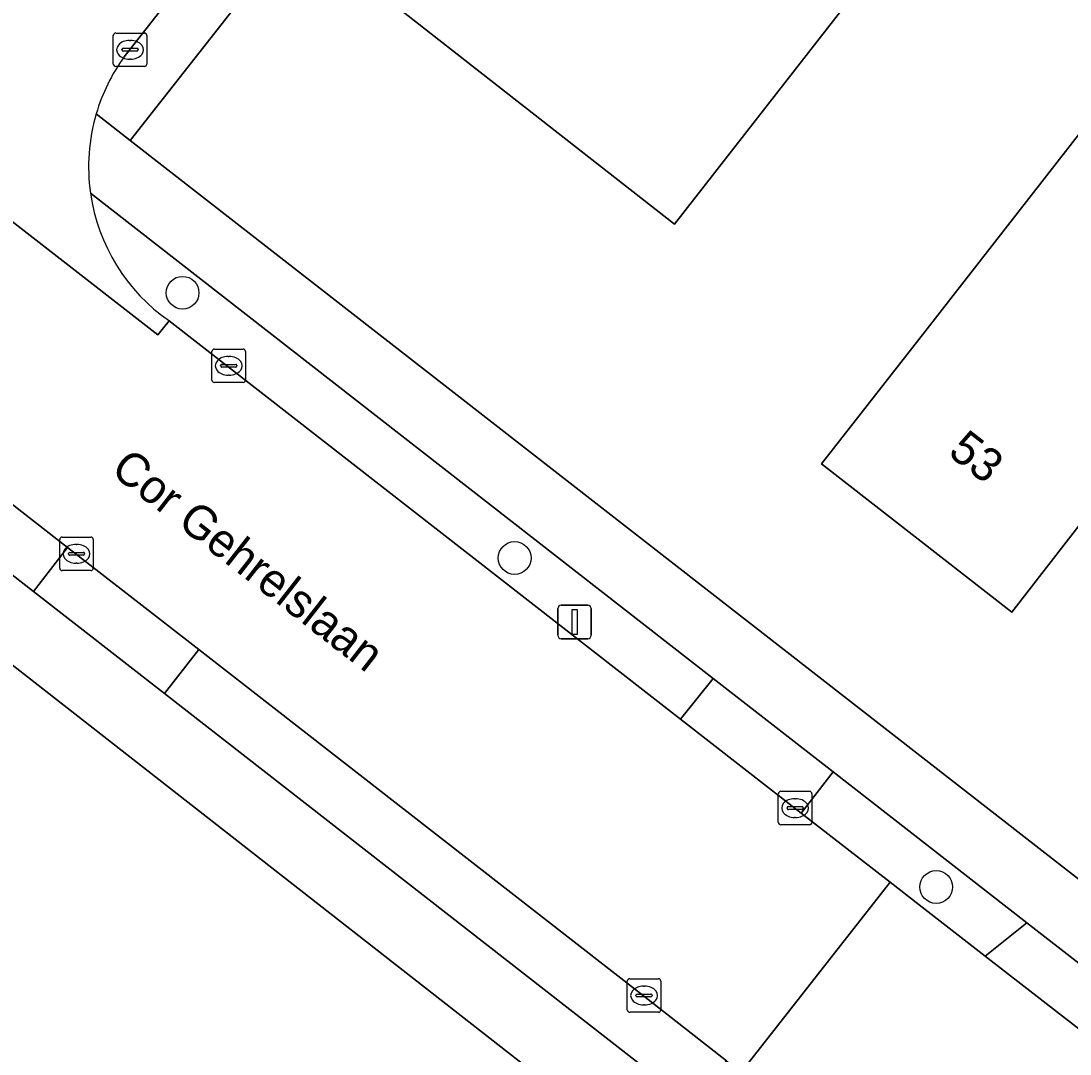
# Model space of a CAD drawing. Extents: x 157320 to 158835, y 386650 to 388491.
# Drawn here: x 158075.99 to 158107.28, y 387187.07 to 387217.9 of the extents above; entities that cross this region are included whole.
import ezdxf

# ---------------------------------------------------------------- set-up
doc = ezdxf.new("R2010")
doc.units = 0
for name, color, linetype in [('IMGEO_Boom', 7, 'Continuous'), ('IMGEO_Erf', 7, 'Continuous'), ('IMGEO_Groenvoorziening', 7, 'Continuous'), ('IMGEO_Kolk', 7, 'Continuous'), ('IMGEO_Lichtmast', 7, 'Continuous'), ('IMGEO_Openbare_ruimte_label', 7, 'Continuous'), ('IMGEO_Pand', 7, 'Continuous'), ('IMGEO_Pand_nummerreeks', 7, 'Continuous'), ('IMGEO_Rijbaan_lokaal_gesloten', 7, 'Continuous'), ('IMGEO_Voetpad_open', 7, 'Continuous')]:
    doc.layers.add(name, color=color, linetype=linetype)

msp = doc.modelspace()

# ---------------------------------------------------------------- linework, layer by layer
at = {"layer": 'IMGEO_Boom'}
for centre in [(158080.808, 387209.792), (158090.712, 387201.874), (158103.289, 387192.056)]:
    msp.add_circle(centre, 0.489, dxfattribs=at)
at = {"layer": 'IMGEO_Erf'}
for points in [[(158090.73, 387228.956), (158079.248, 387214.335), (158109.367, 387190.866), (158137.628, 387206.813)], [(158017.427, 387142.155), (158094.77, 387183.795), (158072.482, 387201.21), (158048.683, 387219.809)]]:
    msp.add_lwpolyline(points, dxfattribs=at)
for points in [[(158103.393, 387218.736), (158101.816, 387219.965), (158095.482, 387211.842), (158086.534, 387218.851), (158093.075, 387227.199), (158096.908, 387224.21), (158099.042, 387226.947), (158105.73, 387221.733)], [(158123.343, 387208.428), (158120.263, 387204.488), (158117.317, 387206.788), (158111.629, 387199.508), (158108.879, 387201.613), (158109.61, 387202.545), (158108.198, 387203.684), (158105.549, 387200.261), (158099.868, 387204.686), (158102.945, 387208.628), (158107.675, 387214.687), (158113.108, 387210.445), (158116.944, 387215.359), (158124.283, 387209.63)]]:
    msp.add_lwpolyline(points, close=True, dxfattribs=at)
at = {"layer": 'IMGEO_Groenvoorziening'}
for points in [[(158078.231, 387215.128), (158079.248, 387214.335), (158090.73, 387228.956), (158089.404, 387230.023), (158079.065, 387216.835)], [(158080.412, 387208.951), (158095.66, 387197.062), (158096.631, 387198.279), (158093.932, 387200.386), (158078.059, 387212.761)], [(158110.765, 387187.271), (158105.993, 387190.987), (158104.752, 387189.993), (158108.123, 387187.373)]]:
    msp.add_lwpolyline(points, dxfattribs=at)
for points in [[(158072.002, 387206.373), (158070.97, 387205.047), (158073.757, 387202.905), (158076.355, 387200.879), (158077.374, 387202.189)], [(158081.29, 387199.14), (158080.268, 387197.827), (158095.882, 387185.65), (158097.032, 387186.869), (158094.555, 387188.809)], [(158100.214, 387195.488), (158099.264, 387194.259), (158101.914, 387192.199), (158102.78, 387191.526), (158104.752, 387189.993), (158105.993, 387190.987)]]:
    msp.add_lwpolyline(points, close=True, dxfattribs=at)
for centre, radius, start, end in [((158083.605, 387213.559), 5.599, 144.1924, 163.7295), ((158083.599, 387213.551), 5.596, 188.1131, 235.2846)]:
    msp.add_arc(centre, radius, start, end, dxfattribs=at)
at = {"layer": 'IMGEO_Kolk'}
for p, q in [((158078.815, 387217.544), (158079.667, 387217.544)), ((158078.74, 387216.618), (158078.74, 387217.47)), ((158079.228, 387217.324), (158079.253, 387217.324)), ((158079.741, 387217.47), (158079.741, 387216.618)), ((158078.999, 387217.038), (158078.999, 387217.05)), ((158079.437, 387217.001), (158079.039, 387217.001)), ((158079.042, 387217.087), (158079.44, 387217.087)), ((158079.483, 387217.05), (158079.483, 387217.038)), ((158079.251, 387216.764), (158079.226, 387216.764)), ((158079.667, 387216.544), (158078.815, 387216.544)), ((158081.759, 387208.112), (158082.611, 387208.112)), ((158081.684, 387207.186), (158081.684, 387208.038)), ((158082.172, 387207.892), (158082.197, 387207.892)), ((158082.685, 387208.038), (158082.685, 387207.186)), ((158081.943, 387207.606), (158081.943, 387207.618)), ((158082.381, 387207.569), (158081.983, 387207.569)), ((158081.986, 387207.655), (158082.384, 387207.655)), ((158082.427, 387207.618), (158082.427, 387207.606)), ((158082.195, 387207.332), (158082.17, 387207.332)), ((158082.611, 387207.112), (158081.759, 387207.112)), ((158077.216, 387202.5), (158078.068, 387202.5)), ((158077.141, 387201.574), (158077.141, 387202.426)), ((158077.629, 387202.28), (158077.654, 387202.28)), ((158078.142, 387202.426), (158078.142, 387201.574)), ((158077.4, 387201.994), (158077.4, 387202.006)), ((158077.838, 387201.957), (158077.44, 387201.957)), ((158077.443, 387202.043), (158077.841, 387202.043)), ((158077.884, 387202.006), (158077.884, 387201.994)), ((158077.652, 387201.72), (158077.627, 387201.72)), ((158078.068, 387201.5), (158077.216, 387201.5)), ((158098.579, 387193.985), (158098.579, 387194.837)), ((158098.654, 387194.911), (158099.506, 387194.911)), ((158099.067, 387194.691), (158099.092, 387194.691)), ((158099.58, 387194.837), (158099.58, 387193.985)), ((158098.838, 387194.405), (158098.838, 387194.417)), ((158099.276, 387194.368), (158098.878, 387194.368)), ((158098.881, 387194.454), (158099.279, 387194.454)), ((158099.322, 387194.417), (158099.322, 387194.405)), ((158099.09, 387194.131), (158099.065, 387194.131)), ((158099.506, 387193.911), (158098.654, 387193.911)), ((158094.073, 387188.39), (158094.073, 387189.242)), ((158094.148, 387189.316), (158095, 387189.316)), ((158094.561, 387189.096), (158094.586, 387189.096)), ((158095.074, 387189.242), (158095.074, 387188.39)), ((158094.332, 387188.81), (158094.332, 387188.822)), ((158094.77, 387188.773), (158094.372, 387188.773)), ((158094.375, 387188.859), (158094.773, 387188.859)), ((158094.816, 387188.822), (158094.816, 387188.81)), ((158094.584, 387188.536), (158094.559, 387188.536)), ((158095, 387188.316), (158094.148, 387188.316))]:
    msp.add_line(p, q, dxfattribs=at)
for points in [[(158078.815, 387217.544), (158079.667, 387217.544)], [(158078.74, 387216.618), (158078.74, 387217.47)], [(158079.741, 387217.47), (158079.741, 387216.618)], [(158079.667, 387216.544), (158078.815, 387216.544)], [(158081.759, 387208.112), (158082.611, 387208.112)], [(158081.684, 387207.186), (158081.684, 387208.038)], [(158082.685, 387208.038), (158082.685, 387207.186)], [(158082.611, 387207.112), (158081.759, 387207.112)], [(158077.216, 387202.5), (158078.068, 387202.5)], [(158077.141, 387201.574), (158077.141, 387202.426)], [(158078.142, 387202.426), (158078.142, 387201.574)], [(158078.068, 387201.5), (158077.216, 387201.5)], [(158098.579, 387193.985), (158098.579, 387194.837)], [(158098.654, 387194.911), (158099.506, 387194.911)], [(158099.58, 387194.837), (158099.58, 387193.985)], [(158099.506, 387193.911), (158098.654, 387193.911)], [(158094.073, 387188.39), (158094.073, 387189.242)], [(158094.148, 387189.316), (158095, 387189.316)], [(158095.074, 387189.242), (158095.074, 387188.39)], [(158095, 387188.316), (158094.148, 387188.316)]]:
    msp.add_lwpolyline(points, dxfattribs=at)
for centre, radius, start, end in [((158078.817, 387217.468), 0.0765, 91.552, 178.448), ((158078.817, 387217.468), 0.0765, 91.552, 178.448), ((158079.665, 387217.468), 0.0765, 1.552, 88.448), ((158079.665, 387217.468), 0.0765, 1.552, 88.448), ((158079.039, 387217.047), 0.0403, 85.8775, 175.7526), ((158079.036, 387217.037), 0.0366, 178.938, 274.7102), ((158079.44, 387217.044), 0.043, 264.8664, 352.4533), ((158079.444, 387217.049), 0.0386, 1.7309, 96.639), ((158078.817, 387216.62), 0.0765, 181.552, 268.448), ((158078.817, 387216.62), 0.0765, 181.552, 268.448), ((158079.665, 387216.62), 0.0765, 271.552, 358.448), ((158079.665, 387216.62), 0.0765, 271.552, 358.448), ((158081.761, 387208.036), 0.0765, 91.552, 178.448), ((158081.761, 387208.036), 0.0765, 91.552, 178.448), ((158082.609, 387208.036), 0.0765, 1.552, 88.448), ((158082.609, 387208.036), 0.0765, 1.552, 88.448), ((158081.983, 387207.615), 0.0403, 85.8775, 175.7526), ((158081.98, 387207.605), 0.0366, 178.938, 274.7102), ((158082.384, 387207.612), 0.043, 264.8664, 352.4533), ((158082.388, 387207.617), 0.0386, 1.7309, 96.639), ((158081.761, 387207.188), 0.0765, 181.552, 268.448), ((158081.761, 387207.188), 0.0765, 181.552, 268.448), ((158082.609, 387207.188), 0.0765, 271.552, 358.448), ((158082.609, 387207.188), 0.0765, 271.552, 358.448), ((158077.218, 387202.424), 0.0765, 91.552, 178.448), ((158077.218, 387202.424), 0.0765, 91.552, 178.448), ((158078.066, 387202.424), 0.0765, 1.552, 88.448), ((158078.066, 387202.424), 0.0765, 1.552, 88.448), ((158077.44, 387202.003), 0.0403, 85.8775, 175.7526), ((158077.437, 387201.993), 0.0366, 178.938, 274.7102), ((158077.841, 387202), 0.043, 264.8664, 352.4533), ((158077.845, 387202.005), 0.0386, 1.7309, 96.639), ((158077.218, 387201.576), 0.0765, 181.552, 268.448), ((158077.218, 387201.576), 0.0765, 181.552, 268.448), ((158078.066, 387201.576), 0.0765, 271.552, 358.448), ((158078.066, 387201.576), 0.0765, 271.552, 358.448), ((158098.656, 387194.835), 0.0765, 91.552, 178.448), ((158098.656, 387194.835), 0.0765, 91.552, 178.448), ((158099.504, 387194.835), 0.0765, 1.552, 88.448), ((158099.504, 387194.835), 0.0765, 1.552, 88.448), ((158098.878, 387194.414), 0.0403, 85.8775, 175.7526), ((158098.875, 387194.404), 0.0366, 178.938, 274.7102), ((158099.279, 387194.411), 0.043, 264.8664, 352.4533), ((158099.283, 387194.416), 0.0386, 1.7309, 96.639), ((158098.656, 387193.987), 0.0765, 181.552, 268.448), ((158098.656, 387193.987), 0.0765, 181.552, 268.448), ((158099.504, 387193.987), 0.0765, 271.552, 358.448), ((158099.504, 387193.987), 0.0765, 271.552, 358.448), ((158094.15, 387189.24), 0.0765, 91.552, 178.448), ((158094.15, 387189.24), 0.0765, 91.552, 178.448), ((158094.998, 387189.24), 0.0765, 1.552, 88.448), ((158094.998, 387189.24), 0.0765, 1.552, 88.448), ((158094.372, 387188.819), 0.0403, 85.8775, 175.7526), ((158094.369, 387188.809), 0.0366, 178.938, 274.7102), ((158094.773, 387188.816), 0.043, 264.8664, 352.4533), ((158094.777, 387188.821), 0.0386, 1.7309, 96.639), ((158094.15, 387188.392), 0.0765, 181.552, 268.448), ((158094.15, 387188.392), 0.0765, 181.552, 268.448), ((158094.998, 387188.392), 0.0765, 271.552, 358.448), ((158094.998, 387188.392), 0.0765, 271.552, 358.448)]:
    msp.add_arc(centre, radius, start, end, dxfattribs=at)
for centre, major_axis, ratio, start_param, end_param in [((158079.227, 387217.044), (-0.387, 0.002), 0.722429, 4.712389, 7.853982), ((158079.252, 387217.044), (-0.39, 0.002), 0.717154, 1.570796, 4.712389), ((158082.171, 387207.612), (-0.387, 0.002), 0.722429, 4.712389, 7.853982), ((158082.196, 387207.612), (-0.39, 0.002), 0.717154, 1.570796, 4.712389), ((158077.628, 387202), (-0.387, 0.002), 0.722429, 4.712389, 7.853982), ((158077.653, 387202), (-0.39, 0.002), 0.717154, 1.570796, 4.712389), ((158099.066, 387194.411), (-0.387, 0.002), 0.722429, 4.712389, 7.853982), ((158099.091, 387194.411), (-0.39, 0.002), 0.717154, 1.570796, 4.712389), ((158094.56, 387188.816), (-0.387, 0.002), 0.722429, 4.712389, 7.853982), ((158094.585, 387188.816), (-0.39, 0.002), 0.717154, 1.570796, 4.712389)]:
    msp.add_ellipse(centre, major_axis=major_axis, ratio=ratio, start_param=start_param, end_param=end_param, dxfattribs=at)
at = {"layer": 'IMGEO_Lichtmast'}
for p, q in [((158092.005, 387199.567), (158092.005, 387200.367)), ((158092.005, 387200.367), (158092.005, 387199.567)), ((158092.105, 387200.467), (158092.895, 387200.467)), ((158092.895, 387200.467), (158092.105, 387200.467)), ((158092.995, 387200.367), (158092.995, 387199.567)), ((158092.995, 387199.567), (158092.995, 387200.367)), ((158092.895, 387199.467), (158092.105, 387199.467)), ((158092.105, 387199.467), (158092.895, 387199.467))]:
    msp.add_line(p, q, dxfattribs=at)
msp.add_lwpolyline([(158092.425, 387200.342), (158092.575, 387200.342), (158092.575, 387199.592), (158092.425, 387199.592), (158092.425, 387200.342)], dxfattribs=at)
for centre, start, end in [((158092.105, 387200.367), 90, 180), ((158092.105, 387200.367), 90, 180), ((158092.895, 387200.367), 0, 90), ((158092.895, 387200.367), 360, 90), ((158092.105, 387199.567), 180, 270), ((158092.105, 387199.567), 180, 270), ((158092.895, 387199.567), 270, 0), ((158092.895, 387199.567), 270, 0)]:
    msp.add_arc(centre, 0.1, start, end, dxfattribs=at)
at = {"layer": 'IMGEO_Pand'}
for points in [[(158095.482, 387211.842), (158101.816, 387219.965), (158103.393, 387218.736), (158105.73, 387221.733), (158099.042, 387226.947), (158096.908, 387224.21), (158093.075, 387227.199), (158086.534, 387218.851)], [(158102.945, 387208.628), (158099.868, 387204.686), (158105.549, 387200.261), (158108.198, 387203.684), (158109.61, 387202.545), (158108.879, 387201.613), (158111.629, 387199.508), (158117.317, 387206.788), (158120.263, 387204.488), (158123.343, 387208.428), (158124.283, 387209.63), (158116.944, 387215.359), (158113.108, 387210.445), (158107.675, 387214.687)]]:
    msp.add_lwpolyline(points, close=True, dxfattribs=at)
at = {"layer": 'IMGEO_Rijbaan_lokaal_gesloten'}
for points in [[(158079.065, 387216.835), (158089.404, 387230.023), (158091.841, 387233.164), (158105.03, 387250), (158110.984, 387257.602)], [(158051.069, 387222.744), (158066.919, 387210.32), (158072.002, 387206.373), (158077.374, 387202.189), (158081.29, 387199.14), (158094.555, 387188.809), (158097.032, 387186.869), (158097.47, 387186.526), (158101.914, 387192.199), (158099.264, 387194.259), (158096.603, 387196.327), (158095.66, 387197.062), (158080.412, 387208.951), (158080.071, 387208.537), (158066.349, 387219.221), (158066.709, 387219.638), (158057.154, 387227.141), (158054.163, 387229.499), (158053.922, 387229.699), (158050.13, 387232.809), (158046.693, 387235.712), (158040.708, 387241.061)], [(158066.709, 387219.638), (158066.349, 387219.221), (158080.071, 387208.537), (158080.412, 387208.951)]]:
    msp.add_lwpolyline(points, dxfattribs=at)
msp.add_lwpolyline([(158114.393, 387182.464), (158114.238, 387182.586), (158108.123, 387187.373), (158104.752, 387189.993), (158102.78, 387191.526), (158101.914, 387192.199), (158097.47, 387186.526), (158098.337, 387185.847), (158101.047, 387183.725), (158105.458, 387180.278), (158107.771, 387178.477), (158110.639, 387176.25), (158110.814, 387176.106), (158111.153, 387175.841), (158115.735, 387181.41)], close=True, dxfattribs=at)
for centre, radius, start, end in [((158083.605, 387213.559), 5.599, 144.1924, 163.7295), ((158083.595, 387213.548), 5.592, 163.5922, 188.0955), ((158083.599, 387213.551), 5.596, 188.1131, 235.2846)]:
    msp.add_arc(centre, radius, start, end, dxfattribs=at)
at = {"layer": 'IMGEO_Voetpad_open'}
for points in [[(158080.268, 387197.827), (158076.355, 387200.879), (158073.757, 387202.905), (158070.97, 387205.047), (158065.904, 387209.026), (158049.964, 387221.488)], [(158048.683, 387219.809), (158072.482, 387201.21), (158094.77, 387183.795), (158096.783, 387182.213), (158098.932, 387180.524), (158101.344, 387178.628), (158103.493, 387176.942), (158106.829, 387174.325), (158123.964, 387160.882)], [(158132.982, 387172.403), (158120.564, 387182.122), (158115.776, 387185.87), (158112.657, 387188.303), (158109.367, 387190.866), (158079.248, 387214.335), (158078.231, 387215.128)], [(158078.059, 387212.761), (158093.932, 387200.386), (158096.631, 387198.279), (158100.214, 387195.488), (158105.993, 387190.987), (158110.765, 387187.271), (158113.821, 387184.89), (158117.456, 387182.04), (158123.126, 387177.595), (158126.265, 387175.145), (158130.559, 387171.787), (158131.398, 387171.136), (158131.766, 387170.849), (158143.406, 387161.763), (158146.71, 387159.183), (158163.192, 387146.32), (158167.78, 387142.729), (158186.369, 387128.092), (158188.327, 387129.07), (158185.407, 387131.357), (158162.416, 387149.364), (158132.982, 387172.403)], [(158128.659, 387159.952), (158125.296, 387162.583), (158112.942, 387172.248), (158109.743, 387174.756), (158106.457, 387177.333), (158104.008, 387179.254), (158100.422, 387182.051), (158096.464, 387185.196), (158095.882, 387185.65), (158080.268, 387197.827)]]:
    msp.add_lwpolyline(points, dxfattribs=at)
for points in [[(158077.374, 387202.189), (158076.355, 387200.879), (158080.268, 387197.827), (158081.29, 387199.14)], [(158099.264, 387194.259), (158100.214, 387195.488), (158096.631, 387198.279), (158095.66, 387197.062), (158096.603, 387196.327)]]:
    msp.add_lwpolyline(points, close=True, dxfattribs=at)
msp.add_arc((158083.595, 387213.548), 5.592, 163.5922, 188.0955, dxfattribs=at)

# ---------------------------------------------------------------- texts
at = {"layer": 'IMGEO_Openbare_ruimte_label'}
msp.add_text('Cor Gehrelslaan', height=1, rotation=322.0295, dxfattribs=at).set_placement((158078.621, 387204.419))
at = {"layer": 'IMGEO_Pand_nummerreeks'}
msp.add_text('53', height=1, rotation=322.0845, dxfattribs=at).set_placement((158103.605, 387204.969))

doc.saveas('drawing.dxf')
